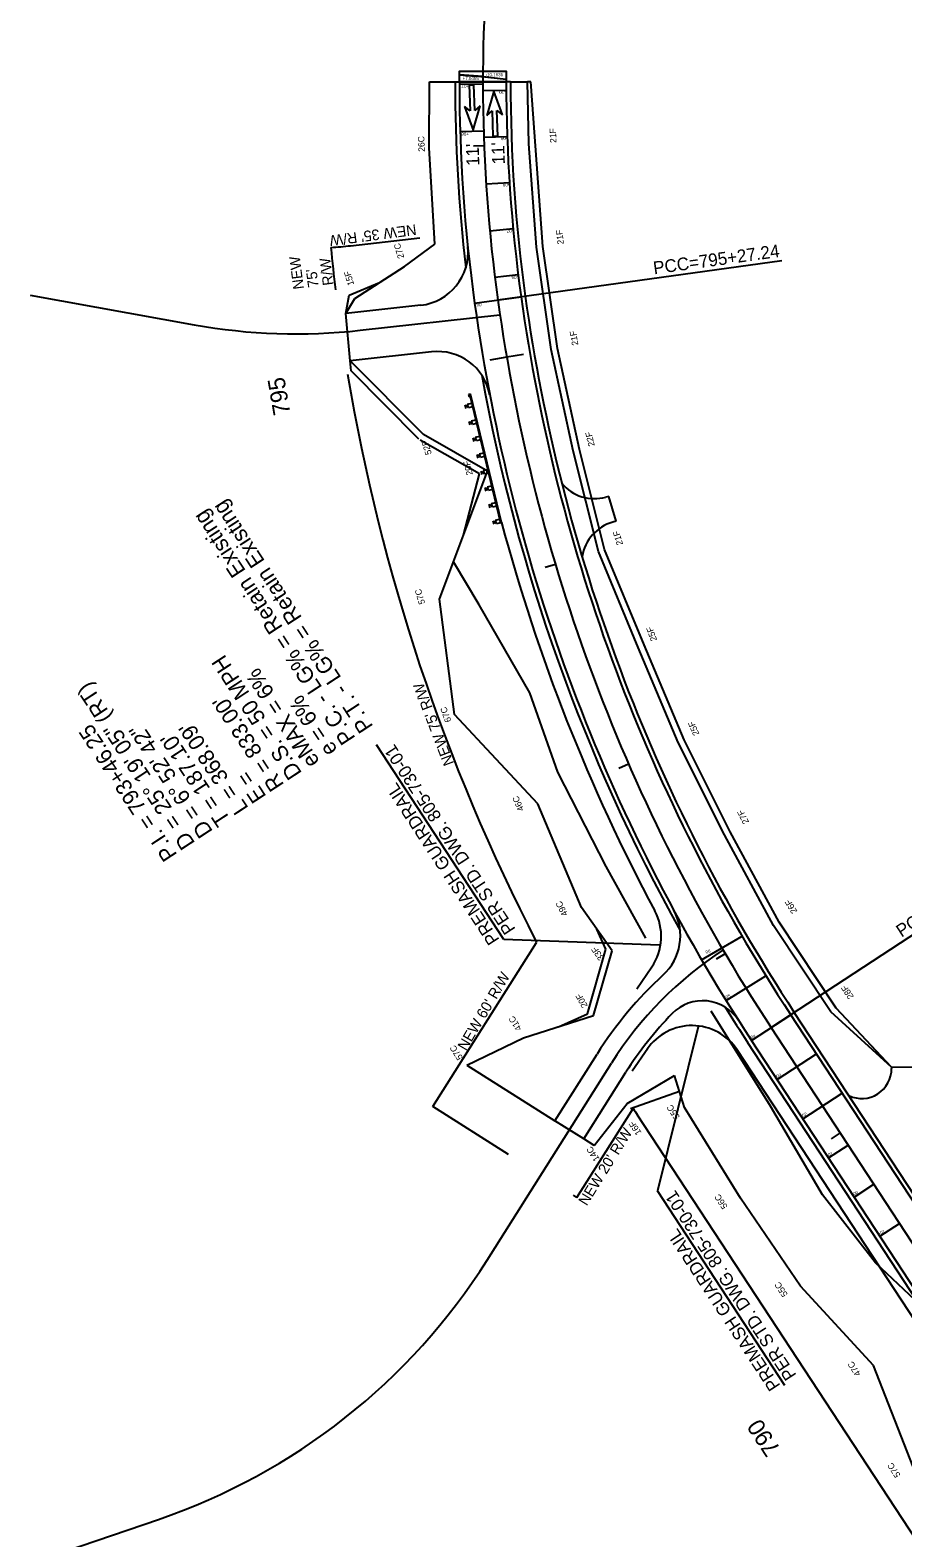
# Model space of a CAD drawing. Extents: x 1551641 to 1624343, y 1119533 to 1136600.
# Drawn here: x 1552124 to 1552534, y 1134310 to 1135018 of the extents above; entities that cross this region are included whole.
import ezdxf

# ---------------------------------------------------------------- set-up
doc = ezdxf.new("R2010")
doc.units = 0
for name, color, linetype in [('RD_HC_Cl', 7, 'Continuous'), ('RD_HC_CL_Rel', 7, 'Continuous'), ('RD_HC_Data', 7, 'Continuous'), ('RD_HC_Data_Tic', 7, 'Continuous'), ('RD_HC_TX_Sta50', 7, 'Continuous'), ('RD_PD_ALT1_TX', 7, 'Continuous'), ('RD_PD_CstnLmt', 7, 'Continuous'), ('RD_PD_CstnLmt_TX', 7, 'Continuous'), ('RD_PD_DR_ErosCtrl', 7, 'Continuous'), ('RD_PD_Driveway', 7, 'Continuous'), ('RD_PD_Final_TrvlWay', 7, 'Continuous'), ('RD_PD_Final_TX', 7, 'Continuous'), ('RD_PD_GR', 7, 'Continuous'), ('RD_PD_PaveShd', 7, 'Continuous'), ('RD_PD_RW', 7, 'Continuous'), ('RD_Sketch7', 7, 'Continuous'), ('RD_TX_Pipe_ElevEX', 7, 'Continuous')]:
    doc.layers.add(name, color=color, linetype=linetype)

msp = doc.modelspace()

# ---------------------------------------------------------------- linework, layer by layer
at = {"layer": 'RD_HC_Cl'}
for p, q in [((1552124.5, 1134893.22), (1552201.52, 1134879.35)), ((1552279.39, 1134876.75), (1552345.07, 1134884.09)), ((1552339, 1134439.95), (1552397.43, 1134532.51)), ((1552089.14, 1134285.64), (1552184.7, 1134318.21))]:
    msp.add_line(p, q, dxfattribs=at)
for centre, radius, start, end in [((1553076.34, 1134992.83), 739.3, 158.33693, 187.91582), ((1552249.39, 1135145.07), 270, 259.78842, 276.37981), ((1552545.41, 1134439.09), 175, 123.11099, 147.73424), ((1552089.55, 1134597.44), 295, 288.81692, 327.73424)]:
    msp.add_arc(centre, radius, start, end, dxfattribs=at)
at = {"layer": 'RD_HC_CL_Rel'}
msp.add_line((1552832.44, 1133999.68), (1552472.39, 1134549.2), dxfattribs=at)
msp.add_arc((1553169.14, 1135005.73), 833, 187.91582, 213.23375, dxfattribs=at)
at = {"layer": 'RD_HC_Data'}
for p, q in [((1552344.08, 1134891.01), (1552477.48, 1134909.56)), ((1552472.39, 1134549.2), (1552585.04, 1134623.01))]:
    msp.add_line(p, q, dxfattribs=at)
at = {"layer": 'RD_HC_Data_Tic'}
for p, q in [((1552337.62, 1134963.45), (1552332.62, 1134963.25)), ((1552348.27, 1134864.1), (1552340.39, 1134862.74)), ((1552356.16, 1134865.46), (1552348.27, 1134864.1)), ((1552371.14, 1134766.81), (1552366.35, 1134765.37)), ((1552405.5, 1134672.96), (1552400.92, 1134670.96)), ((1552450.85, 1134583.9), (1552446.54, 1134581.37)), ((1552504.81, 1134499.72), (1552500.63, 1134496.98))]:
    msp.add_line(p, q, dxfattribs=at)
at = {"layer": 'RD_PD_ALT1_TX'}
for p, q in [((1552326.04, 1134992.44), (1552337.04, 1134992.45)), ((1552337.04, 1134989.45), (1552348.04, 1134989.5)), ((1552326.38, 1134970.12), (1552337.38, 1134970.45)), ((1552337.47, 1134967.45), (1552348.47, 1134967.83)), ((1552338.55, 1134945.48), (1552349.53, 1134946.18)), ((1552340.29, 1134923.55), (1552351.24, 1134924.58)), ((1552342.68, 1134901.68), (1552353.59, 1134903.03)), ((1552333.19, 1134889.5), (1552354.98, 1134892.53)), ((1552439.75, 1134581.09), (1552458.76, 1134592.16)), ((1552451.22, 1134561.97), (1552469.93, 1134573.54)), ((1552463.19, 1134543.17), (1552481.59, 1134555.23)), ((1552475.24, 1134524.77), (1552493.65, 1134536.83)), ((1552487.3, 1134506.37), (1552505.7, 1134518.42)), ((1552499.36, 1134487.97), (1552508.56, 1134493.99)), ((1552511.42, 1134469.56), (1552520.62, 1134475.59)), ((1552523.47, 1134451.16), (1552532.67, 1134457.19))]:
    msp.add_line(p, q, dxfattribs=at)
at = {"layer": 'RD_PD_CstnLmt'}
for p, q in [((1552311.87, 1134962.43), (1552312.04, 1134993.47)), ((1552312.04, 1134993.47), (1552324.04, 1134993.46)), ((1552350.04, 1134993.43), (1552358.04, 1134993.43)), ((1552358.63, 1134964.29), (1552358.04, 1134993.43)), ((1552314.52, 1134917.23), (1552311.87, 1134962.43)), ((1552362.16, 1134915.85), (1552358.63, 1134964.29)), ((1552300.28, 1134906.73), (1552314.52, 1134917.23)), ((1552369.11, 1134867.69), (1552362.16, 1134915.85)), ((1552276.86, 1134891.7), (1552300.28, 1134906.73)), ((1552272.76, 1134884.6), (1552276.86, 1134891.7)), ((1552379.49, 1134820.1), (1552369.11, 1134867.69)), ((1552309.11, 1134827.8), (1552274.75, 1134862.36)), ((1552339.17, 1134810.62), (1552309.11, 1134827.8)), ((1552391.37, 1134772.87), (1552379.49, 1134820.1)), ((1552316.71, 1134750.51), (1552339.17, 1134810.62)), ((1552410.01, 1134727.82), (1552391.37, 1134772.87)), ((1552323.66, 1134696.21), (1552316.71, 1134750.51)), ((1552428.8, 1134683.11), (1552410.01, 1134727.82)), ((1552362.88, 1134654.39), (1552323.66, 1134696.21)), ((1552450.54, 1134639.82), (1552428.8, 1134683.11)), ((1552383.33, 1134605.6), (1552362.88, 1134654.39)), ((1552473.56, 1134597.24), (1552450.54, 1134639.82)), ((1552397.69, 1134585.24), (1552383.33, 1134605.6)), ((1552500.47, 1134556.65), (1552473.56, 1134597.24)), ((1552389.07, 1134554.82), (1552397.69, 1134585.24)), ((1552356.06, 1134544.39), (1552389.07, 1134554.82)), ((1552528.93, 1134530.6), (1552500.47, 1134556.65)), ((1552329.51, 1134531.59), (1552356.06, 1134544.39)), ((1552329.51, 1134531.59), (1552370.9, 1134505.46)), ((1552404.8, 1134513.62), (1552426.95, 1134526.77)), ((1552431.74, 1134511.62), (1552426.95, 1134526.77)), ((1552389.28, 1134493.86), (1552404.8, 1134513.62)), ((1552457.98, 1134469.04), (1552431.74, 1134511.62)), ((1552389.28, 1134493.86), (1552384.42, 1134496.92)), ((1552486.2, 1134427.75), (1552457.98, 1134469.04)), ((1552520.52, 1134390.46), (1552486.2, 1134427.75)), ((1552539.13, 1134342.88), (1552520.52, 1134390.46))]:
    msp.add_line(p, q, dxfattribs=at)
at = {"layer": 'RD_PD_DR_ErosCtrl'}
for p, q in [((1552359.52, 1134993.43), (1552358.04, 1134993.43)), ((1552365.15, 1134916.17), (1552359.52, 1134993.43)), ((1552372.07, 1134868.23), (1552365.15, 1134916.17)), ((1552274.26, 1134893.2), (1552288.57, 1134899.22)), ((1552272.76, 1134884.6), (1552274.26, 1134893.2)), ((1552382.41, 1134820.79), (1552372.07, 1134868.23)), ((1552275.17, 1134857.68), (1552274.75, 1134862.36)), ((1552306.98, 1134825.69), (1552275.17, 1134857.68)), ((1552335.46, 1134809.28), (1552307.62, 1134825.2)), ((1552394.23, 1134773.81), (1552382.41, 1134820.79)), ((1552327.94, 1134780.57), (1552335.46, 1134809.28)), ((1552412.78, 1134728.98), (1552394.23, 1134773.81)), ((1552431.53, 1134684.37), (1552412.78, 1134728.98)), ((1552453.2, 1134641.2), (1552431.53, 1134684.37)), ((1552476.13, 1134598.78), (1552453.2, 1134641.2)), ((1552394.81, 1134586.06), (1552390.51, 1134595.42)), ((1552502.97, 1134558.31), (1552476.13, 1134598.78)), ((1552386.18, 1134555.64), (1552394.81, 1134586.06)), ((1552528.93, 1134530.6), (1552502.97, 1134558.31)), ((1552372.57, 1134549.61), (1552386.18, 1134555.64)), ((1552429.34, 1134519.2), (1552406.33, 1134511.04))]:
    msp.add_line(p, q, dxfattribs=at)
at = {"layer": 'RD_PD_Driveway'}
for p, q in [((1552307.9, 1134888.53), (1552272.76, 1134884.6)), ((1552274.75, 1134862.36), (1552272.76, 1134884.6)), ((1552312.97, 1134866.63), (1552274.75, 1134862.36)), ((1552396.18, 1134798.76), (1552394.83, 1134798.39)), ((1552399.63, 1134787.05), (1552396.18, 1134798.76)), ((1552399.63, 1134787.05), (1552398.07, 1134786.62)), ((1552370.9, 1134505.46), (1552390.67, 1134536.78)), ((1552528.93, 1134530.6), (1552545.93, 1134530.76)), ((1552528.93, 1134530.6), (1552528.94, 1134530.01)), ((1552384.42, 1134496.92), (1552404.2, 1134528.24)), ((1552384.42, 1134496.92), (1552370.9, 1134505.46))]:
    msp.add_line(p, q, dxfattribs=at)
for centre, radius, start, end in [((1552305.12, 1134913.38), 25, 276.37981, 5.88181), ((1552315.75, 1134841.79), 25, 10.87425, 96.37981), ((1552389.51, 1134817.67), 20, 219.71347, 285.42639), ((1552403.39, 1134767.34), 20, 105.42639, 171.1406), ((1552404.77, 1134592.34), 25, 312.54279, 28.40574), ((1552545.41, 1134439.09), 183, 132.54279, 147.73424), ((1552440.26, 1134541.81), 20, 32.47574, 135.66872), ((1552545.41, 1134439.09), 167, 135.66872, 147.73424), ((1552514.94, 1134529.88), 14, 244.23647, 0.53797)]:
    msp.add_arc(centre, radius, start, end, dxfattribs=at)
at = {"layer": 'RD_PD_Final_TrvlWay'}
for p, q in [((1552326.04, 1134993.45), (1552348.04, 1134993.44)), ((1552841.65, 1134005.71), (1552481.59, 1134555.23)), ((1552823.24, 1133993.65), (1552463.19, 1134543.17))]:
    msp.add_line(p, q, dxfattribs=at)
for centre, radius, start, end in [((1553076.34, 1134992.83), 750.3, 179.95198, 187.91582), ((1553076.34, 1134992.83), 728.3, 179.95198, 187.91582), ((1553169.14, 1135005.73), 822, 187.91582, 213.23375), ((1553169.14, 1135005.73), 844, 187.91582, 213.23375)]:
    msp.add_arc(centre, radius, start, end, dxfattribs=at)
at = {"layer": 'RD_PD_Final_TX'}
for p, q in [((1552332.87, 1134991.93), (1552330.62, 1134991.85)), ((1552330.62, 1134991.85), (1552331.05, 1134979.86)), ((1552333.29, 1134979.94), (1552332.87, 1134991.93)), ((1552342.16, 1134989.05), (1552338.88, 1134977.68)), ((1552346.23, 1134977.94), (1552342.16, 1134989.05)), ((1552328.42, 1134981.87), (1552332.49, 1134970.76)), ((1552331.05, 1134979.86), (1552328.42, 1134981.87)), ((1552332.49, 1134970.76), (1552335.77, 1134982.13)), ((1552335.77, 1134982.13), (1552333.29, 1134979.94)), ((1552338.88, 1134977.68), (1552341.36, 1134979.87)), ((1552341.36, 1134979.87), (1552341.78, 1134967.87)), ((1552344.03, 1134967.95), (1552343.6, 1134979.94)), ((1552343.6, 1134979.94), (1552346.23, 1134977.94)), ((1552341.78, 1134967.87), (1552344.03, 1134967.95)), ((1552346.97, 1134590.58), (1552287.09, 1134681.98)), ((1552419.91, 1134587.87), (1552346.97, 1134590.58)), ((1552438.06, 1134549.51), (1552418.97, 1134472.49)), ((1552478.86, 1134381.1), (1552418.97, 1134472.49))]:
    msp.add_line(p, q, dxfattribs=at)
at = {"layer": 'RD_PD_GR'}
for p, q in [((1552328.64, 1134841.77), (1552329.05, 1134840.07)), ((1552329.85, 1134842.06), (1552331.8, 1134842.53)), ((1552330.26, 1134840.36), (1552329.85, 1134842.06)), ((1552331.28, 1134846.78), (1552330.31, 1134846.54)), ((1552330.31, 1134846.54), (1552330.55, 1134845.57)), ((1552330.55, 1134845.57), (1552331.03, 1134845.69)), ((1552331.03, 1134845.69), (1552345.34, 1134786.39)), ((1552345.83, 1134786.51), (1552331.28, 1134846.78)), ((1552331.8, 1134842.53), (1552332.21, 1134840.83)), ((1552330.06, 1134841.21), (1552328.84, 1134840.92)), ((1552332.21, 1134840.83), (1552330.26, 1134840.36)), ((1552331.73, 1134834.28), (1552333.67, 1134834.75)), ((1552333.67, 1134834.75), (1552334.08, 1134833.05)), ((1552330.51, 1134833.99), (1552330.92, 1134832.29)), ((1552331.93, 1134833.43), (1552330.72, 1134833.14)), ((1552332.14, 1134832.58), (1552331.73, 1134834.28)), ((1552334.08, 1134833.05), (1552332.14, 1134832.58)), ((1552332.39, 1134826.21), (1552332.8, 1134824.51)), ((1552333.81, 1134825.66), (1552332.6, 1134825.36)), ((1552333.61, 1134826.51), (1552335.55, 1134826.98)), ((1552334.02, 1134824.81), (1552333.61, 1134826.51)), ((1552335.96, 1134825.28), (1552334.02, 1134824.81)), ((1552335.55, 1134826.98), (1552335.96, 1134825.28)), ((1552334.27, 1134818.44), (1552334.68, 1134816.74)), ((1552335.69, 1134817.88), (1552334.47, 1134817.59)), ((1552335.48, 1134818.73), (1552337.43, 1134819.2)), ((1552335.89, 1134817.03), (1552335.48, 1134818.73)), ((1552337.84, 1134817.5), (1552335.89, 1134817.03)), ((1552337.43, 1134819.2), (1552337.84, 1134817.5)), ((1552336.14, 1134810.66), (1552336.55, 1134808.96)), ((1552337.56, 1134810.1), (1552336.35, 1134809.81)), ((1552337.36, 1134810.95), (1552339.3, 1134811.42)), ((1552337.77, 1134809.25), (1552337.36, 1134810.95)), ((1552339.71, 1134809.72), (1552337.77, 1134809.25)), ((1552339.3, 1134811.42), (1552339.71, 1134809.72)), ((1552338.02, 1134802.88), (1552338.43, 1134801.18)), ((1552339.44, 1134802.33), (1552338.23, 1134802.03)), ((1552339.24, 1134803.18), (1552341.18, 1134803.65)), ((1552339.65, 1134801.48), (1552339.24, 1134803.18)), ((1552341.59, 1134801.95), (1552339.65, 1134801.48)), ((1552341.18, 1134803.65), (1552341.59, 1134801.95)), ((1552339.9, 1134795.11), (1552340.31, 1134793.41)), ((1552341.32, 1134794.55), (1552340.1, 1134794.26)), ((1552341.11, 1134795.4), (1552343.06, 1134795.87)), ((1552341.52, 1134793.7), (1552341.11, 1134795.4)), ((1552343.47, 1134794.17), (1552341.52, 1134793.7)), ((1552343.06, 1134795.87), (1552343.47, 1134794.17)), ((1552341.77, 1134787.33), (1552342.18, 1134785.63)), ((1552343.19, 1134786.77), (1552341.98, 1134786.48)), ((1552342.99, 1134787.62), (1552344.93, 1134788.09)), ((1552343.4, 1134785.92), (1552342.99, 1134787.62)), ((1552345.34, 1134786.39), (1552343.4, 1134785.92)), ((1552344.93, 1134788.09), (1552345.34, 1134786.39)), ((1552345.34, 1134786.39), (1552345.83, 1134786.51)), ((1552409.3, 1134567.38), (1552416.34, 1134577.71)), ((1552414.43, 1134539.38), (1552407.15, 1134528.69)), ((1552552.99, 1134391.51), (1552456.5, 1134538.79))]:
    msp.add_line(p, q, dxfattribs=at)
for centre, radius, start, end in [((1553169.14, 1135005.73), 852, 194.90936, 208.12621), ((1552395.27, 1134592.06), 25.5, 325.73561, 28.12621), ((1552435.26, 1134524.66), 25.5, 33.23375, 145.73561)]:
    msp.add_arc(centre, radius, start, end, dxfattribs=at)
at = {"layer": 'RD_PD_PaveShd'}
for p, q in [((1552324.04, 1134993.46), (1552326.04, 1134993.45)), ((1552350.04, 1134993.43), (1552348.04, 1134993.44)), ((1552568.73, 1134425.88), (1552483.26, 1134556.32)), ((1552546.98, 1134411.64), (1552461.51, 1134542.07))]:
    msp.add_line(p, q, dxfattribs=at)
for centre, radius, start, end in [((1553076.34, 1134992.83), 752.3, 179.95198, 186.61689), ((1553076.34, 1134992.83), 726.3, 179.95198, 187.91582), ((1553169.14, 1135005.73), 820, 187.91582, 213.23375), ((1553169.14, 1135005.73), 846, 190.21951, 209.06048), ((1553169.14, 1135005.73), 846, 211.8915, 213.23375)]:
    msp.add_arc(centre, radius, start, end, dxfattribs=at)
at = {"layer": 'RD_PD_RW'}
for p, q in [((1552274.95, 1134916.5), (1552307.47, 1134920.13)), ((1552313.58, 1134512.08), (1552362.29, 1134589.25)), ((1552349.09, 1134489.66), (1552313.58, 1134512.08)), ((1552381.23, 1134469.38), (1552407.63, 1134511.2)), ((1552647.6, 1134144.95), (1552409.65, 1134508.1)), ((1552381.23, 1134469.38), (1552379.53, 1134470.44))]:
    msp.add_line(p, q, dxfattribs=at)
for centre, radius, start, end in [((1552249.39, 1135145.07), 230, 274.06733, 276.37981), ((1553076.34, 1134992.83), 814.3, 185.43822, 186.84635), ((1553169.14, 1135005.73), 908, 189.4862, 207.30204), ((1553169.14, 1135005.73), 908, 212.99983, 213.23375)]:
    msp.add_arc(centre, radius, start, end, dxfattribs=at)
at = {"layer": 'RD_Sketch7'}
for p, q in [((1552335.31, 1134747.76), (1552323.27, 1134768.07)), ((1552359.07, 1134706.44), (1552335.31, 1134747.76)), ((1552372.24, 1134669.14), (1552359.07, 1134706.44)), ((1552394.91, 1134624.9), (1552372.24, 1134669.14)), ((1552413.56, 1134591.26), (1552394.91, 1134624.9)), ((1552472.06, 1134512.27), (1552444.27, 1134556.88)), ((1552496.56, 1134470.59), (1552472.06, 1134512.27)), ((1552521.43, 1134438.78), (1552496.56, 1134470.59)), ((1552540.08, 1134421.23), (1552521.43, 1134438.78))]:
    msp.add_line(p, q, dxfattribs=at)
at = {"layer": 'RD_TX_Pipe_ElevEX'}
for q in [(1552326.04, 1134996.69), (1552348.04, 1134994.78)]:
    msp.add_line((1552337.04, 1134995.91), q, dxfattribs=at)
msp.add_lwpolyline([(1552326.04, 1134993.45), (1552326.04, 1134998.45), (1552348.04, 1134998.44), (1552348.04, 1134993.44)], close=True, dxfattribs=at)
msp.add_lwpolyline([(1552326.04, 1134996.69), (1552329.59, 1134996.45), (1552336.07, 1134996), (1552336.6, 1134995.95), (1552348.04, 1134994.78)], dxfattribs=at)

# ---------------------------------------------------------------- texts
at = {"layer": 'RD_HC_Data'}
for s, height, rotation, p in [('PCC=795+27.24', 6, 7.91582, (1552417.46, 1134903)), ('P.C. - LG% = Retain Existing', 7.5, 123.23375, (1552277.43, 1134685.21)), ('P.T. - LG% = Retain Existing', 7.5, 123.23375, (1552285.79, 1134690.7)), ('D.S. = 50 MPH', 7.5, 123.23375, (1552252.33, 1134668.77)), ('eMAX = 6%', 7.5, 123.23375, (1552260.7, 1134674.25)), ('    = 25%%d 19\' 05" (RT)', 7.5, 123.23375, (1552202.15, 1134635.89)), ("R = 833.00'", 7.5, 123.23375, (1552243.97, 1134663.29)), ('e = 6%', 7.5, 123.23375, (1552269.06, 1134679.73)), ('P.I. = 793+46.25', 7.5, 123.23375, (1552193.78, 1134630.41)), ('D = 6%%d 52\' 42"', 7.5, 123.23375, (1552210.51, 1134641.37)), ("T = 187.10'", 7.5, 123.23375, (1552218.88, 1134646.85)), ("L = 368.09'", 7.5, 123.23375, (1552227.24, 1134652.33)), ('E = ', 7.5, 123.23375, (1552235.61, 1134657.81)), ('D', 7.5, 123.23375, (1552202.15, 1134635.89)), ('PC=791+59.15', 6, 33.23375, (1552533.59, 1134591.42))]:
    msp.add_text(s, height=height, rotation=rotation, dxfattribs=at).set_placement(p)
at = {"layer": 'RD_HC_TX_Sta50'}
for s, rotation, p in [('795', 99.7998, (1552246.77, 1134837.6)), ('790', 123.23375, (1552477.09, 1134351.18))]:
    msp.add_text(s, height=8, rotation=rotation, dxfattribs=at).set_placement(p)
at = {"layer": 'RD_PD_ALT1_TX'}
for s, rotation, p in [('+07', 179.95198, (1552330.56, 1134992.13)), ('-10', 182.25696, (1552347.71, 1134989.32)), ('+06', 179.95198, (1552330.47, 1134969.68)), ('-09', 182.25696, (1552348.44, 1134967.67)), ('-08', 182.25696, (1552349.41, 1134945.91)), ('-07', 182.25696, (1552351.24, 1134924.14)), ('-06', 182.25696, (1552353.5, 1134902.41)), ('06', 182.25696, (1552336.37, 1134889.58)), ('06', 20.03896, (1552441.92, 1134583.85)), ('05', 20.03896, (1552451.32, 1134562.77)), ('04', 20.03896, (1552463.09, 1134543.83)), ('03', 20.03896, (1552475.17, 1134525.5)), ('02', 20.03896, (1552487.2, 1134507.22)), ('01', 20.03896, (1552499.36, 1134488.69)), ('00', 20.03896, (1552511.25, 1134470.41)), ('-01', 20.03896, (1552523.22, 1134451.87))]:
    msp.add_text(s, height=1.5, rotation=rotation, dxfattribs=at).set_placement(p)
at = {"layer": 'RD_PD_CstnLmt_TX'}
for s, rotation, p in [('21F', 92.27697, (1552371.62, 1134964.81)), ('26C', 92.27697, (1552309.82, 1134960.67)), ('21F', 96.15198, (1552375.09, 1134917.24)), ('27C', 107.11061, (1552300.19, 1134910.94)), ('15F', 106.91841, (1552276.66, 1134898.29)), ('21F', 99.7895, (1552381.92, 1134869.9)), ('22F', 103.22863, (1552389.6, 1134822.61)), ('52F', 107.11061, (1552313.09, 1134818.75)), ('20F', 103.22863, (1552332.35, 1134809.02)), ('21F', 106.66775, (1552402.89, 1134776.27)), ('57C', 106.66775, (1552310.01, 1134748.5)), ('25F', 110.10687, (1552418.9, 1134731.34)), ('67C', 110.10687, (1552322.31, 1134693.27)), ('25F', 113.546, (1552438.77, 1134687.13)), ('46C', 113.546, (1552356.47, 1134651.59)), ('27F', 116.98511, (1552462.12, 1134645.72)), ('49C', 116.98511, (1552377.1, 1134602.42)), ('26F', 120.42424, (1552484.77, 1134603.82)), ('33F', 124.38155, (1552394.15, 1134581.95)), ('28F', 123.23375, (1552511.34, 1134563.78)), ('20F', 118.35672, (1552386.37, 1134559.49)), ('41C', 122.60119, (1552355.45, 1134548.8)), ('57C', 122.60119, (1552327.81, 1134535.12)), ('55C', 123.23375, (1552429.67, 1134507.25)), ('16F', 122.60119, (1552411.67, 1134499.85)), ('14C', 122.60119, (1552391.98, 1134487.54)), ('56C', 123.23375, (1552452.12, 1134465.2)), ('55C', 123.23375, (1552480.35, 1134423.92)), ('47C', 123.23375, (1552514.67, 1134386.63)), ('57C', 123.23375, (1552533.28, 1134339.04))]:
    msp.add_text(s, height=3, rotation=rotation, dxfattribs=at).set_placement(p)
at = {"layer": 'RD_PD_Final_TX'}
for s, rotation, p in [("11'", 92.02049, (1552335.43, 1134954.06)), ("11'", 92.02049, (1552347.41, 1134954.78)), ('PER STD. DWG. 805-730-01', 123.23375, (1552352.57, 1134595.45)), ('PREMASH GUARDRAIL', 123.23375, (1552345.04, 1134590.52)), ('PER STD. DWG. 805-730-01', 123.23375, (1552484.46, 1134385.96)), ('PREMASH GUARDRAIL', 123.23375, (1552476.93, 1134381.03))]:
    msp.add_text(s, height=6, rotation=rotation, dxfattribs=at).set_placement(p)
at = {"layer": 'RD_PD_RW'}
for s, rotation, p in [("NEW 35' R/W", 187.44688, (1552305.5, 1134926.56)), ('NEW ', 97.44688, (1552253.07, 1134896.31)), ('R/W', 97.44688, (1552266.96, 1134898.12)), ("75' ", 97.44688, (1552260.01, 1134897.22)), ("NEW 75' R/W", 111.01426, (1552323.6, 1134673.36)), ("NEW 60' R/W", 59.57924, (1552329.18, 1134537.98)), ("NEW 20' R/W", 58.26158, (1552385.84, 1134465.16))]:
    msp.add_text(s, height=5, rotation=rotation, dxfattribs=at).set_placement(p)
at = {"layer": 'RD_TX_Pipe_ElevEX'}
for s, p in [('-10.1636', (1552338.35, 1134996.1)), ('+7.0455', (1552327.56, 1134994.32))]:
    msp.add_text(s, height=1.5, rotation=359.95198, dxfattribs=at).set_placement(p)

doc.saveas('drawing.dxf')
